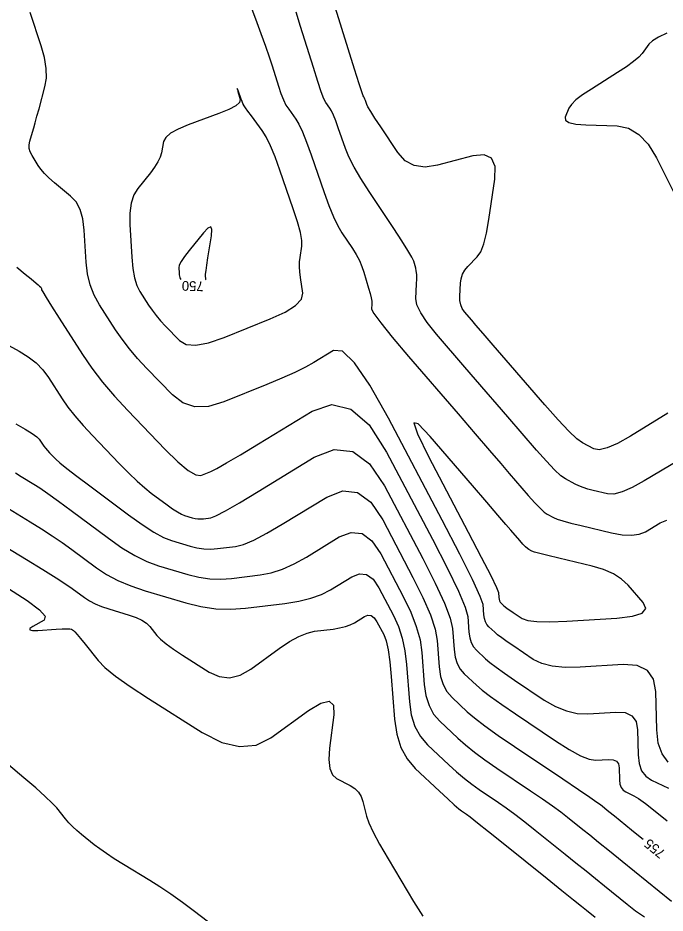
# Model space of a CAD drawing. Extents: x 2082232 to 2083549, y 592624 to 593832.
# Drawn here: x 2082578.9 to 2082625.4, y 592714.1 to 592778.4 of the extents above; entities that cross this region are included whole.
import ezdxf

# ---------------------------------------------------------------- set-up
doc = ezdxf.new("R2010")
doc.units = 0
doc.layers.add('DT_X_Contour_Major', color=7, linetype='Continuous')
doc.layers.add('DT_X_Contour_Minor', color=7, linetype='Continuous')

msp = doc.modelspace()

# ---------------------------------------------------------------- linework, layer by layer
at = {"layer": 'DT_X_Contour_Major'}
for points in [[(2082592.806, 592762.692), (2082592.841, 592763.149), (2082592.757, 592763.338), (2082592.552, 592763.26), (2082592.228, 592762.916), (2082591.205, 592761.642), (2082590.87, 592761.207), (2082590.634, 592760.857), (2082590.495, 592760.591), (2082590.454, 592760.41), (2082590.477, 592760.042), (2082590.488, 592759.913), (2082590.507, 592759.805), (2082590.534, 592759.718), (2082590.567, 592759.65), (2082590.614, 592759.577)], [(2082592.365, 592759.532), (2082592.395, 592759.563), (2082592.411, 592759.631), (2082592.384, 592759.808), (2082592.387, 592759.94), (2082592.417, 592760.203), (2082592.472, 592760.596), (2082592.554, 592761.12), (2082592.806, 592762.692)], [(2082578.756, 592749.205), (2082579.431, 592748.825), (2082579.938, 592748.516), (2082580.277, 592748.276), (2082580.448, 592748.107), (2082580.679, 592747.747), (2082580.776, 592747.607), (2082580.894, 592747.457), (2082581.032, 592747.296), (2082581.191, 592747.125), (2082581.643, 592746.654), (2082581.921, 592746.403), (2082582.419, 592746.001), (2082583.134, 592745.449), (2082584.069, 592744.747), (2082586.852, 592742.673), (2082587.828, 592741.974), (2082588.667, 592741.432), (2082589.37, 592741.048), (2082589.937, 592740.82), (2082591.267, 592740.424), (2082591.764, 592740.301), (2082592.257, 592740.23), (2082592.747, 592740.212), (2082593.234, 592740.246), (2082594.527, 592740.405), (2082595.101, 592740.549), (2082595.852, 592740.861), (2082596.781, 592741.341), (2082597.887, 592741.988), (2082601.075, 592743.939), (2082602.222, 592744.386), (2082603.274, 592744.262), (2082604.231, 592743.568), (2082605.093, 592742.304), (2082607.264, 592738.173), (2082607.983, 592736.729), (2082608.511, 592735.493), (2082608.85, 592734.465), (2082608.999, 592733.647), (2082609.143, 592731.743), (2082609.241, 592731.07), (2082609.428, 592730.481), (2082609.703, 592729.973), (2082610.066, 592729.549), (2082611.152, 592728.528), (2082611.67, 592728.084), (2082612.41, 592727.519), (2082613.372, 592726.832), (2082614.555, 592726.022), (2082618.006, 592723.702), (2082619.142, 592722.938), (2082619.963, 592722.384), (2082620.469, 592722.041), (2082620.659, 592721.909), (2082620.747, 592721.839), (2082620.833, 592721.77), (2082621.024, 592721.614), (2082621.321, 592721.373), (2082621.723, 592721.046), (2082622.938, 592720.058), (2082623.443, 592719.647), (2082623.782, 592719.371)], [(2082594.005, 592712.351), (2082591.593, 592714.177), (2082590.714, 592714.83), (2082589.884, 592715.42), (2082589.104, 592715.946), (2082588.374, 592716.408), (2082586.493, 592717.557), (2082585.833, 592717.968), (2082585.264, 592718.342), (2082584.785, 592718.677), (2082584.397, 592718.973), (2082583.482, 592719.713), (2082583.153, 592719.991), (2082582.851, 592720.273), (2082582.576, 592720.558), (2082582.329, 592720.847), (2082581.706, 592721.619), (2082581.382, 592721.972), (2082580.879, 592722.451), (2082580.197, 592723.057), (2082579.334, 592723.788), (2082576.796, 592725.907)]]:
    msp.add_lwpolyline(points, dxfattribs=at)
at = {"layer": 'DT_X_Contour_Minor'}
for points in [[(2082594.838, 592781.307), (2082595.963, 592778.292), (2082596.354, 592777.233), (2082596.683, 592776.318), (2082596.948, 592775.547), (2082597.151, 592774.92), (2082597.61, 592773.439), (2082597.784, 592772.92), (2082597.965, 592772.472), (2082598.152, 592772.096), (2082598.345, 592771.791), (2082598.867, 592771.074), (2082599.082, 592770.712), (2082599.336, 592770.165), (2082599.629, 592769.431), (2082599.96, 592768.512), (2082600.894, 592765.811), (2082601.236, 592764.872), (2082601.562, 592764.078), (2082601.872, 592763.431), (2082602.165, 592762.93), (2082602.925, 592761.787), (2082603.19, 592761.36), (2082603.415, 592760.933), (2082603.6, 592760.508), (2082603.745, 592760.084), (2082604.08, 592758.955), (2082604.188, 592758.566), (2082604.264, 592758.248), (2082604.306, 592758), (2082604.315, 592757.821), (2082604.295, 592757.439), (2082604.455, 592757.12), (2082604.95, 592756.449), (2082605.78, 592755.426), (2082606.945, 592754.05), (2082610.498, 592749.914), (2082611.727, 592748.483), (2082612.75, 592747.293), (2082613.567, 592746.344), (2082614.178, 592745.635), (2082615.532, 592744.066), (2082615.998, 592743.54), (2082616.38, 592743.139), (2082616.677, 592742.862), (2082616.891, 592742.71), (2082617.348, 592742.47), (2082617.6, 592742.366), (2082618.015, 592742.236), (2082618.592, 592742.08), (2082619.331, 592741.897), (2082621.517, 592741.375), (2082622.284, 592741.233), (2082622.944, 592741.199), (2082623.497, 592741.274), (2082623.944, 592741.456), (2082624.995, 592742.087), (2082625.477, 592742.274)], [(2082625.547, 592749.98), (2082622.863, 592748.324), (2082621.944, 592747.8), (2082621.2, 592747.472), (2082620.631, 592747.34), (2082620.237, 592747.403), (2082619.421, 592747.832), (2082619.023, 592748.123), (2082618.441, 592748.675), (2082617.676, 592749.489), (2082616.728, 592750.563), (2082613.955, 592753.776), (2082613.02, 592754.859), (2082612.298, 592755.696), (2082611.786, 592756.289), (2082611.487, 592756.637), (2082610.97, 592757.239), (2082610.803, 592757.479), (2082610.689, 592757.749), (2082610.627, 592758.048), (2082610.619, 592758.377), (2082610.667, 592759.294), (2082610.714, 592759.627), (2082610.82, 592759.939), (2082610.985, 592760.229), (2082611.208, 592760.498), (2082611.882, 592761.188), (2082612.123, 592761.55), (2082612.341, 592762.118), (2082612.537, 592762.893), (2082612.71, 592763.874), (2082613.141, 592766.766), (2082613.164, 592767.684), (2082612.908, 592768.268), (2082612.373, 592768.519), (2082611.56, 592768.437), (2082609.021, 592767.774), (2082608.13, 592767.644), (2082607.361, 592767.751), (2082606.713, 592768.094), (2082606.187, 592768.675), (2082604.947, 592770.539), (2082604.536, 592771.163), (2082604.232, 592771.638), (2082604.035, 592771.965), (2082603.946, 592772.142), (2082603.851, 592772.415), (2082603.818, 592772.508), (2082603.788, 592772.583), (2082603.762, 592772.638), (2082603.741, 592772.675), (2082603.688, 592772.748), (2082603.606, 592772.979), (2082603.401, 592773.618), (2082603.073, 592774.665), (2082602.621, 592776.12), (2082601.252, 592780.545)], [(2082625.586, 592724.902), (2082625.138, 592725.5), (2082624.86, 592726.273), (2082624.753, 592727.221), (2082624.695, 592729.983), (2082624.531, 592730.88), (2082624.084, 592731.501), (2082623.354, 592731.845), (2082622.341, 592731.913), (2082619.26, 592731.726), (2082618.183, 592731.708), (2082617.264, 592731.797), (2082616.503, 592731.991), (2082615.899, 592732.291), (2082614.499, 592733.232), (2082614.019, 592733.56), (2082613.632, 592733.837), (2082613.336, 592734.062), (2082613.132, 592734.236), (2082612.709, 592734.633), (2082612.568, 592734.798), (2082612.461, 592734.995), (2082612.389, 592735.225), (2082612.351, 592735.486), (2082612.295, 592736.227), (2082612.096, 592736.813), (2082611.541, 592738.018), (2082610.629, 592739.842), (2082609.362, 592742.283), (2082605.508, 592749.618), (2082604.177, 592751.985), (2082603.076, 592753.583), (2082602.204, 592754.412), (2082601.561, 592754.473), (2082600.153, 592753.611), (2082599.547, 592753.27), (2082598.782, 592752.892), (2082597.86, 592752.478), (2082596.78, 592752.028), (2082593.69, 592750.778), (2082592.59, 592750.458), (2082591.608, 592750.434), (2082590.743, 592750.706), (2082589.996, 592751.275), (2082588.161, 592753.187), (2082587.505, 592753.898), (2082586.913, 592754.597), (2082586.386, 592755.285), (2082585.922, 592755.961), (2082584.773, 592757.749), (2082584.389, 592758.444), (2082584.1, 592759.186), (2082583.906, 592759.977), (2082583.806, 592760.815), (2082583.668, 592763.115), (2082583.568, 592763.915), (2082583.373, 592764.588), (2082583.083, 592765.136), (2082582.698, 592765.557), (2082581.543, 592766.513), (2082581.144, 592766.859), (2082580.814, 592767.182), (2082580.552, 592767.481), (2082580.357, 592767.757), (2082579.931, 592768.461), (2082579.8, 592768.723), (2082579.728, 592768.982), (2082579.715, 592769.238), (2082579.761, 592769.49), (2082579.961, 592770.158), (2082580.046, 592770.45), (2082580.153, 592770.827), (2082580.281, 592771.287), (2082580.43, 592771.831), (2082580.856, 592773.394), (2082580.958, 592774.018), (2082580.947, 592774.719), (2082580.821, 592775.498), (2082580.58, 592776.353), (2082579.788, 592778.736)], [(2082626.314, 592746.579), (2082623.852, 592745.099), (2082622.995, 592744.625), (2082622.273, 592744.312), (2082621.684, 592744.162), (2082621.23, 592744.174), (2082620.195, 592744.421), (2082619.823, 592744.52), (2082619.483, 592744.629), (2082619.174, 592744.749), (2082618.897, 592744.881), (2082618.201, 592745.247), (2082617.875, 592745.479), (2082617.422, 592745.901), (2082616.84, 592746.513), (2082616.13, 592747.315), (2082614.066, 592749.706), (2082613.294, 592750.601), (2082612.524, 592751.495), (2082611.757, 592752.386), (2082610.992, 592753.276), (2082608.957, 592755.645), (2082608.292, 592756.471), (2082607.823, 592757.172), (2082607.55, 592757.749), (2082607.472, 592758.202), (2082607.527, 592759.243), (2082607.538, 592759.608), (2082607.53, 592759.921), (2082607.504, 592760.182), (2082607.459, 592760.392), (2082607.314, 592760.881), (2082607.184, 592761.166), (2082606.903, 592761.653), (2082606.47, 592762.342), (2082605.886, 592763.233), (2082604.126, 592765.878), (2082603.524, 592766.815), (2082603.039, 592767.644), (2082602.671, 592768.365), (2082602.42, 592768.977), (2082601.906, 592770.463), (2082601.723, 592770.97), (2082601.562, 592771.374), (2082601.422, 592771.675), (2082601.304, 592771.875), (2082601.016, 592772.269), (2082600.879, 592772.537), (2082600.683, 592773.045), (2082600.429, 592773.792), (2082600.115, 592774.78), (2082599.202, 592777.732), (2082598.875, 592778.774)], [(2082625.482, 592777.248), (2082624.88, 592776.969), (2082624.449, 592776.704), (2082624.188, 592776.454), (2082623.717, 592775.803), (2082623.474, 592775.535), (2082623.099, 592775.216), (2082622.592, 592774.847), (2082621.952, 592774.428), (2082620.07, 592773.244), (2082619.44, 592772.825), (2082618.961, 592772.457), (2082618.634, 592772.138), (2082618.458, 592771.87), (2082618.189, 592771.222), (2082618.207, 592771.006), (2082618.46, 592770.842), (2082618.949, 592770.732), (2082619.674, 592770.675), (2082621.921, 592770.592), (2082622.729, 592770.426), (2082623.467, 592769.989), (2082624.134, 592769.282), (2082624.732, 592768.305), (2082626.234, 592765.338)], [(2082599.193, 592759.702), (2082599.143, 592760.109), (2082599.122, 592760.486), (2082599.129, 592760.834), (2082599.164, 592761.154), (2082599.295, 592761.966), (2082599.293, 592762.362), (2082599.189, 592762.942), (2082598.983, 592763.705), (2082598.674, 592764.651), (2082597.717, 592767.419), (2082597.367, 592768.376), (2082597.036, 592769.171), (2082596.724, 592769.803), (2082596.431, 592770.274), (2082595.674, 592771.313), (2082595.425, 592771.654), (2082595.247, 592771.899), (2082595.14, 592772.047), (2082595.104, 592772.098), (2082595.101, 592772.107), (2082595.091, 592772.136), (2082595.061, 592772.216), (2082595.013, 592772.346), (2082594.945, 592772.526), (2082594.74, 592773.075), (2082594.68, 592773.229), (2082594.655, 592773.279), (2082594.663, 592773.224), (2082594.706, 592773.065), (2082594.867, 592772.503), (2082594.816, 592772.28), (2082594.545, 592772.035), (2082594.052, 592771.767), (2082593.338, 592771.476), (2082591.14, 592770.67), (2082590.411, 592770.369), (2082589.873, 592770.067), (2082589.527, 592769.766), (2082589.372, 592769.466), (2082589.212, 592768.666), (2082589.118, 592768.351), (2082588.954, 592768.006), (2082588.722, 592767.632), (2082588.42, 592767.228), (2082587.522, 592766.111), (2082587.235, 592765.635), (2082587.044, 592765.044), (2082586.951, 592764.339), (2082586.955, 592763.519), (2082587.096, 592761.181), (2082587.172, 592760.368), (2082587.292, 592759.684), (2082587.458, 592759.128), (2082587.67, 592758.7), (2082588.294, 592757.729), (2082588.545, 592757.362), (2082588.832, 592756.989), (2082589.153, 592756.609), (2082589.509, 592756.223), (2082590.505, 592755.185), (2082590.987, 592754.907), (2082591.683, 592754.852), (2082592.595, 592755.018), (2082593.723, 592755.406), (2082597.017, 592756.738), (2082598.09, 592757.228), (2082598.838, 592757.698), (2082599.262, 592758.149), (2082599.361, 592758.579), (2082599.193, 592759.702)], [(2082578.827, 592760.445), (2082579.44, 592759.95), (2082579.854, 592759.616), (2082580.068, 592759.441), (2082580.375, 592759.187), (2082580.475, 592759.1), (2082580.548, 592759.026), (2082580.593, 592758.968), (2082580.609, 592758.924), (2082580.615, 592758.826), (2082580.695, 592758.672), (2082580.932, 592758.283), (2082581.326, 592757.658), (2082581.876, 592756.799), (2082583.551, 592754.193), (2082584.226, 592753.208), (2082584.995, 592752.206), (2082585.857, 592751.186), (2082586.813, 592750.15), (2082589.488, 592747.364), (2082590.399, 592746.464), (2082591.128, 592745.853), (2082591.674, 592745.53), (2082592.037, 592745.495), (2082592.763, 592745.789), (2082593.181, 592745.995), (2082593.891, 592746.394), (2082594.892, 592746.986), (2082596.185, 592747.77), (2082600.022, 592750.119), (2082601.435, 592750.596), (2082602.798, 592750.265), (2082604.109, 592749.127), (2082605.37, 592747.18), (2082608.663, 592740.913), (2082609.747, 592738.804), (2082610.531, 592737.176), (2082611.014, 592736.031), (2082611.196, 592735.367), (2082611.281, 592734.238), (2082611.34, 592733.84), (2082611.45, 592733.49), (2082611.613, 592733.19), (2082611.828, 592732.939), (2082612.472, 592732.334), (2082612.783, 592732.068), (2082613.234, 592731.724), (2082613.825, 592731.303), (2082614.555, 592730.804), (2082616.689, 592729.369), (2082617.485, 592728.904), (2082618.269, 592728.585), (2082619.044, 592728.412), (2082619.808, 592728.385), (2082621.832, 592728.508), (2082622.497, 592728.464), (2082622.977, 592728.238), (2082623.271, 592727.83), (2082623.378, 592727.24), (2082623.416, 592725.426), (2082623.487, 592724.803), (2082623.669, 592724.295), (2082623.963, 592723.903), (2082624.369, 592723.625), (2082625.602, 592723.037)], [(2082577.192, 592755.411), (2082579.012, 592754.419), (2082579.655, 592754.022), (2082580.219, 592753.574), (2082580.705, 592753.077), (2082581.112, 592752.53), (2082582.094, 592751.003), (2082582.506, 592750.409), (2082583.005, 592749.77), (2082583.593, 592749.088), (2082584.267, 592748.361), (2082586.184, 592746.365), (2082586.866, 592745.67), (2082587.475, 592745.083), (2082588.012, 592744.603), (2082588.476, 592744.231), (2082589.615, 592743.382), (2082590.014, 592743.096), (2082590.358, 592742.874), (2082590.646, 592742.717), (2082590.878, 592742.624), (2082591.422, 592742.462), (2082591.626, 592742.411), (2082591.828, 592742.382), (2082592.028, 592742.375), (2082592.228, 592742.389), (2082592.757, 592742.454), (2082593.119, 592742.591), (2082593.807, 592742.951), (2082594.822, 592743.536), (2082596.163, 592744.345), (2082600.174, 592746.8), (2082601.618, 592747.362), (2082602.943, 592747.206), (2082604.147, 592746.333), (2082605.231, 592744.742), (2082607.963, 592739.543), (2082608.865, 592737.766), (2082609.521, 592736.334), (2082609.932, 592735.248), (2082610.098, 592734.507), (2082610.212, 592732.991), (2082610.29, 592732.455), (2082610.439, 592731.985), (2082610.658, 592731.582), (2082610.947, 592731.244), (2082611.812, 592730.431), (2082612.23, 592730.074), (2082612.836, 592729.612), (2082613.63, 592729.046), (2082614.612, 592728.375), (2082617.48, 592726.447), (2082618.466, 592725.817), (2082619.274, 592725.373), (2082619.904, 592725.116), (2082620.356, 592725.045), (2082621.322, 592725.104), (2082621.64, 592725.082), (2082621.87, 592724.974), (2082622.01, 592724.779), (2082622.061, 592724.498), (2082622.079, 592723.631), (2082622.113, 592723.334), (2082622.2, 592723.091), (2082622.341, 592722.903), (2082622.535, 592722.771), (2082623.123, 592722.49), (2082623.438, 592722.299), (2082623.941, 592721.936), (2082624.632, 592721.4), (2082625.512, 592720.693)], [(2082621.896, 592735.26), (2082623.025, 592735.391), (2082623.715, 592735.618), (2082623.968, 592735.942), (2082623.782, 592736.363), (2082622.704, 592737.615), (2082622.239, 592738.052), (2082621.653, 592738.425), (2082620.945, 592738.734), (2082620.115, 592738.979), (2082617.742, 592739.547), (2082616.953, 592739.738), (2082616.366, 592739.887), (2082615.981, 592739.994), (2082615.798, 592740.058), (2082615.581, 592740.172), (2082615.479, 592740.245), (2082615.337, 592740.377), (2082615.156, 592740.568), (2082614.934, 592740.818), (2082614.289, 592741.565), (2082613.936, 592741.975), (2082613.359, 592742.646), (2082612.558, 592743.578), (2082611.533, 592744.771), (2082608.503, 592748.299), (2082607.643, 592749.202), (2082607.334, 592749.264), (2082607.578, 592748.485), (2082608.373, 592746.867), (2082611.23, 592741.429), (2082612.169, 592739.628), (2082612.842, 592738.304), (2082613.25, 592737.457), (2082613.393, 592737.086), (2082613.42, 592736.734), (2082613.438, 592736.61), (2082613.472, 592736.5), (2082613.523, 592736.407), (2082613.59, 592736.328), (2082613.791, 592736.139), (2082613.889, 592736.056), (2082614.03, 592735.949), (2082614.214, 592735.817), (2082614.442, 592735.661), (2082615.109, 592735.213), (2082615.496, 592735.076), (2082616.157, 592735.002), (2082617.093, 592734.99), (2082618.303, 592735.041), (2082621.896, 592735.26)], [(2082578.734, 592745.688), (2082579.159, 592745.42), (2082580.059, 592744.873), (2082580.479, 592744.601), (2082581.065, 592744.193), (2082581.818, 592743.65), (2082582.736, 592742.972), (2082585.406, 592740.982), (2082586.382, 592740.3), (2082587.305, 592739.745), (2082588.176, 592739.317), (2082588.996, 592739.017), (2082591.111, 592738.386), (2082591.902, 592738.191), (2082592.687, 592738.078), (2082593.466, 592738.049), (2082594.24, 592738.103), (2082596.297, 592738.357), (2082597.083, 592738.508), (2082597.897, 592738.771), (2082598.74, 592739.146), (2082599.612, 592739.632), (2082601.975, 592741.079), (2082602.826, 592741.41), (2082603.606, 592741.318), (2082604.316, 592740.804), (2082604.955, 592739.866), (2082606.564, 592736.803), (2082607.1, 592735.691), (2082607.502, 592734.651), (2082607.769, 592733.683), (2082607.901, 592732.787), (2082608.074, 592730.495), (2082608.192, 592729.686), (2082608.417, 592728.976), (2082608.748, 592728.365), (2082609.185, 592727.855), (2082610.492, 592726.626), (2082611.035, 592726.146), (2082611.681, 592725.629), (2082612.432, 592725.075), (2082613.287, 592724.484), (2082615.706, 592722.858), (2082616.551, 592722.283), (2082617.274, 592721.776), (2082617.874, 592721.338), (2082618.352, 592720.969), (2082619.462, 592720.077), (2082619.95, 592719.683), (2082620.582, 592719.172), (2082621.357, 592718.543), (2082622.276, 592717.795), (2082624.919, 592715.646), (2082625.824, 592714.921)], [(2082577.592, 592743.506), (2082579.791, 592742.17), (2082580.596, 592741.67), (2082581.362, 592741.171), (2082582.087, 592740.673), (2082582.773, 592740.176), (2082584.548, 592738.854), (2082585.266, 592738.379), (2082586.09, 592737.948), (2082587.02, 592737.559), (2082588.055, 592737.213), (2082590.955, 592736.348), (2082592.039, 592736.08), (2082593.116, 592735.926), (2082594.185, 592735.886), (2082595.246, 592735.96), (2082598.067, 592736.308), (2082599.064, 592736.466), (2082599.942, 592736.681), (2082600.699, 592736.95), (2082601.337, 592737.276), (2082602.876, 592738.218), (2082603.43, 592738.434), (2082603.938, 592738.374), (2082604.4, 592738.039), (2082604.816, 592737.428), (2082605.865, 592735.433), (2082606.218, 592734.653), (2082606.492, 592733.809), (2082606.687, 592732.9), (2082606.803, 592731.927), (2082607.005, 592729.247), (2082607.143, 592728.301), (2082607.406, 592727.471), (2082607.792, 592726.757), (2082608.304, 592726.16), (2082609.833, 592724.723), (2082610.399, 592724.208), (2082610.953, 592723.74), (2082611.492, 592723.319), (2082612.019, 592722.946), (2082613.405, 592722.014), (2082613.96, 592721.628), (2082614.585, 592721.168), (2082615.28, 592720.635), (2082616.044, 592720.029), (2082618.177, 592718.314), (2082618.953, 592717.69), (2082619.681, 592717.102), (2082620.363, 592716.55), (2082620.997, 592716.035), (2082622.626, 592714.711), (2082623.242, 592714.233), (2082623.871, 592713.792)], [(2082576.024, 592741.593), (2082579.524, 592739.467), (2082580.714, 592738.739), (2082581.658, 592738.149), (2082582.356, 592737.696), (2082582.809, 592737.381), (2082583.689, 592736.726), (2082584.046, 592736.49), (2082584.456, 592736.276), (2082584.921, 592736.082), (2082585.439, 592735.909), (2082586.893, 592735.475), (2082587.394, 592735.302), (2082587.808, 592735.108), (2082588.135, 592734.894), (2082588.374, 592734.658), (2082588.894, 592734.001), (2082589.155, 592733.729), (2082589.547, 592733.404), (2082590.07, 592733.027), (2082590.724, 592732.597), (2082592.642, 592731.381), (2082593.368, 592731.052), (2082594.106, 592730.976), (2082594.857, 592731.153), (2082595.62, 592731.584), (2082597.672, 592733.068), (2082598.407, 592733.563), (2082599.075, 592733.934), (2082599.674, 592734.182), (2082600.205, 592734.305), (2082601.531, 592734.469), (2082601.999, 592734.543), (2082602.41, 592734.643), (2082602.764, 592734.768), (2082603.061, 592734.92), (2082603.776, 592735.357), (2082604.034, 592735.457), (2082604.27, 592735.43), (2082604.485, 592735.274), (2082604.678, 592734.99), (2082605.165, 592734.064), (2082605.336, 592733.616), (2082605.482, 592732.967), (2082605.605, 592732.118), (2082605.704, 592731.067), (2082605.936, 592728), (2082606.094, 592726.916), (2082606.394, 592725.966), (2082606.837, 592725.149), (2082607.422, 592724.465), (2082609.173, 592722.82), (2082609.764, 592722.269), (2082610.224, 592721.85), (2082610.553, 592721.563), (2082610.751, 592721.408), (2082611.105, 592721.17), (2082611.369, 592720.973), (2082611.896, 592720.56), (2082612.685, 592719.932), (2082613.737, 592719.089), (2082616.891, 592716.552), (2082617.955, 592715.696), (2082618.781, 592715.032), (2082619.369, 592714.558), (2082619.718, 592714.275), (2082620.332, 592713.776)], [(2082578.238, 592737.383), (2082579.584, 592736.52), (2082580.458, 592735.855), (2082580.86, 592735.386), (2082580.79, 592735.115), (2082579.974, 592734.652), (2082579.768, 592734.504), (2082579.762, 592734.408), (2082579.954, 592734.363), (2082580.347, 592734.369), (2082581.659, 592734.454), (2082582.096, 592734.478), (2082582.425, 592734.485), (2082582.646, 592734.475), (2082582.758, 592734.448), (2082582.911, 592734.353), (2082583.006, 592734.267), (2082583.174, 592734.078), (2082583.416, 592733.787), (2082583.732, 592733.393), (2082584.672, 592732.208), (2082585.161, 592731.704), (2082585.925, 592731.082), (2082586.963, 592730.341), (2082588.275, 592729.482), (2082592.141, 592727.034), (2082593.536, 592726.322), (2082594.822, 592726.024), (2082596, 592726.139), (2082597.07, 592726.667), (2082599.777, 592728.626), (2082600.651, 592729.157), (2082601.244, 592729.279), (2082601.554, 592728.993), (2082601.583, 592728.299), (2082601.284, 592725.904), (2082601.231, 592725.094), (2082601.297, 592724.462), (2082601.482, 592724.007), (2082601.787, 592723.729), (2082602.757, 592723.225), (2082603.087, 592723.011), (2082603.35, 592722.748), (2082603.545, 592722.435), (2082603.673, 592722.073), (2082603.926, 592721.041), (2082604.094, 592720.559), (2082604.41, 592719.885), (2082604.872, 592719.02), (2082605.482, 592717.964), (2082607.304, 592714.893), (2082607.983, 592713.848)]]:
    msp.add_lwpolyline(points, dxfattribs=at)

# ---------------------------------------------------------------- texts
at = {"layer": 'DT_X_Contour_Major'}
for s, rotation, p in [('750', 178.51176, (2082592.248, 592759.424)), ('755', 140.82605, (2082625.43, 592718.48))]:
    msp.add_text(s, height=0.7, rotation=rotation, dxfattribs=at).set_placement(p)

doc.saveas('drawing.dxf')
